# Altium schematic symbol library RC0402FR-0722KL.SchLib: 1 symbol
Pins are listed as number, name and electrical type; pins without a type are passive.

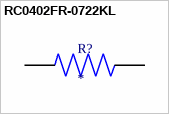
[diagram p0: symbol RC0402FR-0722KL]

## RC0402FR-0722KL
designator R?
22 kOhms Â±1% 0.063W, 1/16W Chip Resistor 0402 (1005 Metric) Moisture Resistant Thick Film; MF: Yageo; MP: RC0402FR-0722KL
footprint RESC1005X40N
pins: 1, 2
